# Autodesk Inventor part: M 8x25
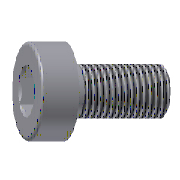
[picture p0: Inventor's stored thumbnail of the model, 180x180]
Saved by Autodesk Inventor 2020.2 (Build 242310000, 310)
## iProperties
IsCustomPart: 0
Manager: www.cadconsulting.pl
Company: Fabian Stasiak CAD Consulting
Created: 2014-02
Part Number: M 8x25
Material: Stal, miękka
Description: Socket Head Cap Screw DIN 912 - 12.9
Document SubType Name: Modeling
Designer: F.Stasiak
Standard Revision: 1
Manufacturer: DME
Language: pl-PL
Size Designation: 8x25
Categories: <MemberInstance><Categories><Category DisplayName="Forma wtryskowa" InternalName="349578f2-f4d4-4954-8c09-8e99297a61c0" Mnemonic="MOLD"><Category DisplayName="C
Mass: 0.133121 g
Surface Area: 2.01441 cm^2
Volume: 0.133121 cm^3
Density: 7.85 g/cm^3
Appearance: Częściowo polerowana
Catalog Web Link: www.expertbooks.pl
Author: F.Stasiak
Subject: Zbiór ćwiczeń. Autodesk Inventor 2020. Kurs Professional
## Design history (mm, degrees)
sketch "Sketch1"
  geometry: L1 (0, -31.6)-(0, 14.6) reference; L2 (3.464, 8)-(6.5, 8); L3 (6.5, 8)-(6.5, 0); L4 (6.5, 0)-(4, 0); L5 (4, 0)-(4, -25); L6 (4, -25)-(0, -25); L7 (0, 2.197)-(0, -25); L8 (0, 2.197)-(3, 4); L9 (3, 4)-(3, 7.536); L10 (3, 7.536)-(3.464, 8); 1 further point
  constraints: 18 end point, 4 vertical, 3 horizontal, 2 point on line
  dimensions: "d0" = 13 diameter of L3 L1 (= dk); "d1" = 8 distance between parallel lines of L4 L2 (= k); "d2" = 8 diameter of L5 L1 (= d); "d3" = 25 distance between parallel lines of L6 L4 (= L); "d4" = 59 deg angle of L1 L8; "d5" = 45 deg angle of L1 L10; "d6" = 6 diameter of L9 L1 (= sw); "d7" = 6.9282 diameter of L2.start L1 (= 1.1547 x sw); "d8" = 4 distance from line of L8.end L2 (= t)
revolve "Revolution1" sketch "Sketch1" stored, may be unused: angle "d44" = 90 deg
sketch "Sketch2"
  geometry: L1 (0, 3.464)-(3, 1.732); L2 (3, 1.732)-(3, -1.732); L3 (3, -1.732)-(0, -3.464); L4 (0, -3.464)-(-3, -1.732); L5 (-3, -1.732)-(-3, 1.732); L6 (-3, 1.732)-(0, 3.464); 3 further points
  constraints: 12 end point, 2 vertical alignment, 1 coincident, 14 other
extrude "Extrusion1" cut sketch "Sketch2" taper "d9" = 0 deg; stored distance "d45" = 10
thread "Thread1" dims "d10" = 22 (= b), "d11" = 0
chamfer "Chamfer1" distance "d12" = 0.625 (= 0.5 x P); stored, may be unused: second distance "d50" = 2, angle "d51" = 45 deg
fillet "Fillet1" dims "d13" = 0.625 (= 0.5 x P)
body "Solid1"
other parameters: "d" = 8 [user parameter; used in 1 equation term], "L" = 25 [user parameter; used in 1 equation term], "dk" = 13 [user parameter; used in 1 equation term], "b" = 22 [user parameter; used in 1 equation term], "k" = 8 [user parameter; used in 1 equation term], "sw" = 6 [user parameter; used in 2 equation terms], "t" = 4 [user parameter; used in 1 equation term], "P" = 1.25 [user parameter; used in 2 equation terms], "d14" = 0, "d15" = 0, "d55" = 0
